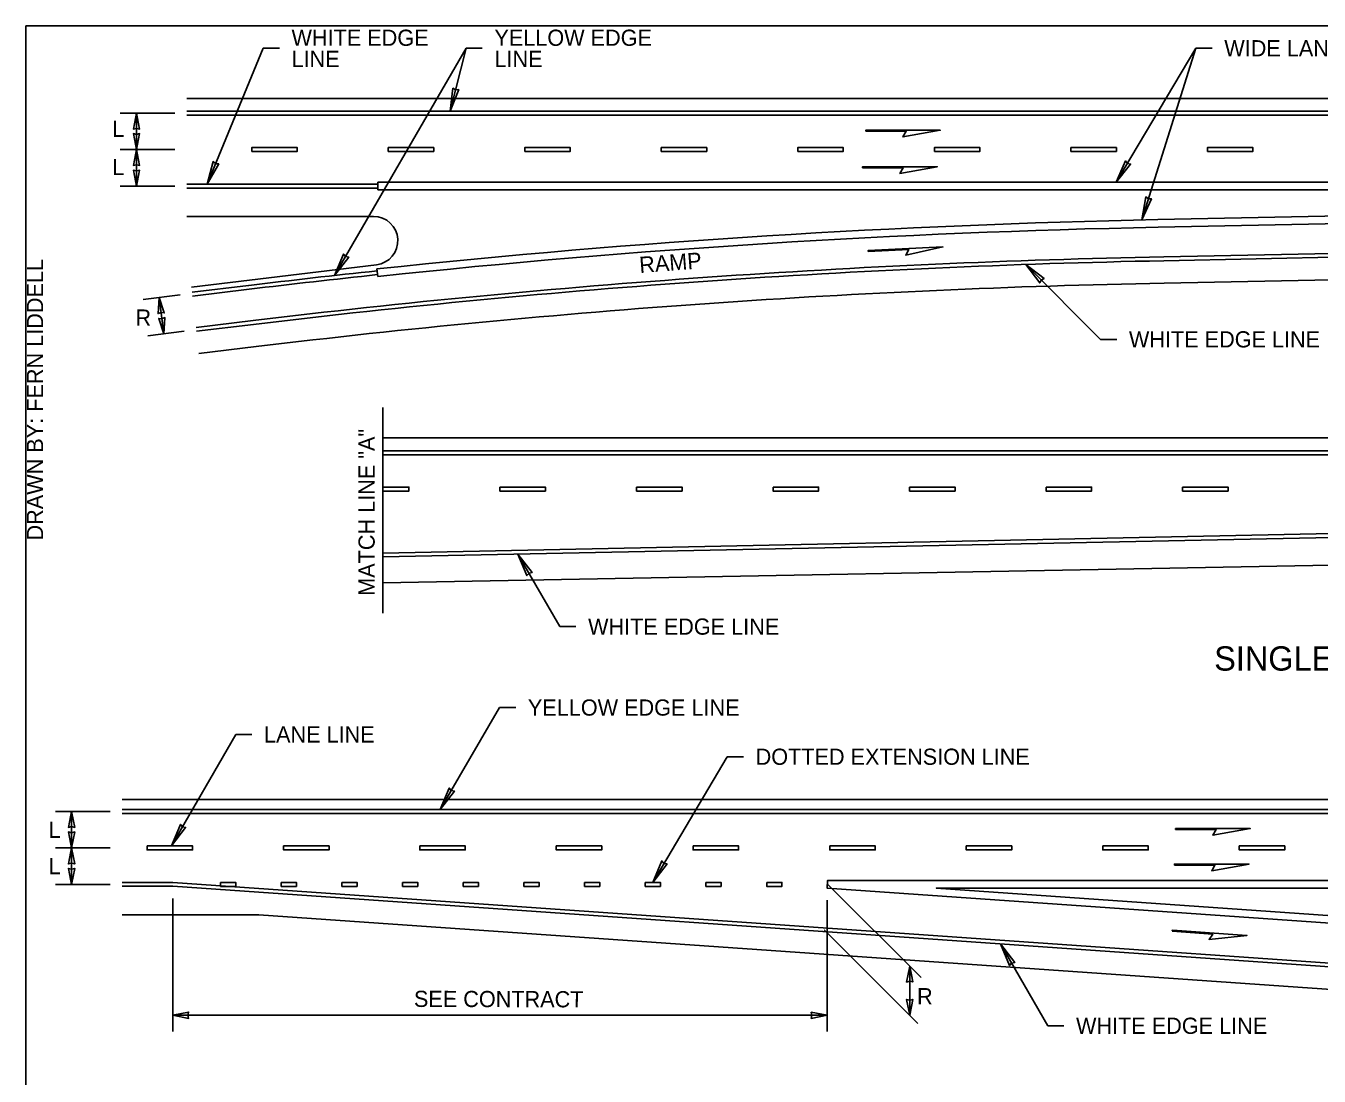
# Model space of a CAD drawing. Extents: x 99862 to 103151, y 100164 to 102240.
# Drawn here: x 99862 to 101141, y 101202 to 102240 of the extents above; entities that cross this region are included whole.
import ezdxf

# ---------------------------------------------------------------- set-up
doc = ezdxf.new("R2010")
doc.units = 0
for name, color, linetype in [('Level 1', 7, 'Continuous'), ('Level 15', 7, 'Continuous'), ('Level 2', 7, 'Continuous'), ('Level 20', 7, 'Continuous'), ('Level 3', 7, 'Continuous'), ('Level 4', 7, 'Continuous'), ('Level 5', 7, 'Continuous'), ('Level 6', 7, 'Continuous'), ('Level 62', 7, 'Continuous')]:
    doc.layers.add(name, color=color, linetype=linetype)

msp = doc.modelspace()

# ---------------------------------------------------------------- linework, layer by layer
at = {"layer": 'Level 1'}
msp.add_lwpolyline([(99862, 100164.2), (103151, 100164.2), (103151, 102240.2), (99862, 102240.2)], close=True, dxfattribs=at)
at = {"layer": 'Level 15'}
for p, q in [((100096.7, 102218.1), (100041.3, 102083.9)), ((100112.7, 102218.1), (100096.7, 102218.1)), ((100297.3, 102218.1), (100167.3, 101993.5)), ((100297.3, 102218.1), (100281.6, 102155.8)), ((100313.3, 102218.1), (100297.3, 102218.1)), ((100940.1, 102085.6), (101019, 102218.1)), ((100965.3, 102048.4), (101019, 102218.1)), ((101035, 102218.1), (101019, 102218.1)), ((99955.3, 102153.9), (100009.3, 102153.9)), ((99971.3, 102153.9), (99971.3, 102118)), ((99955.3, 102118), (100009.3, 102118)), ((99971.3, 102118), (99971.3, 102081.9)), ((99955.3, 102081.9), (100009.3, 102081.9)), ((100850.6, 102004.4), (100924.7, 101930.4)), ((99978, 101969.7), (100014.7, 101974.5)), ((99993.8, 101971.7), (99998.5, 101935.9)), ((99982.6, 101933.8), (100018.6, 101938.5)), ((100924.7, 101930.4), (100940.7, 101930.4)), ((100389.9, 101646.5), (100348.6, 101718.2)), ((100389.9, 101646.5), (100405.9, 101646.5)), ((100271.8, 101465.6), (100330.4, 101566.5)), ((100330.4, 101566.5), (100346.4, 101566.5)), ((100005.9, 101429.7), (100069.5, 101539.9)), ((100069.5, 101539.9), (100085.5, 101539.9)), ((100482, 101393.6), (100555.6, 101517.9)), ((100555.6, 101517.9), (100571.6, 101517.9)), ((99945.2, 101463.7), (99891.2, 101463.7)), ((99907.2, 101463.7), (99907.2, 101427.7)), ((99945.2, 101427.7), (99891.2, 101427.7)), ((99907.2, 101427.7), (99907.2, 101391.7)), ((99945.2, 101391.7), (99891.2, 101391.7)), ((100747.2, 101299.7), (100655.1, 101391.7)), ((100007.2, 101377.9), (100007.2, 101246.4)), ((100654.2, 101376), (100654.2, 101246.4)), ((100744, 101254.3), (100651.4, 101346.9)), ((100825.8, 101332.8), (100872.4, 101252)), ((100735.9, 101311), (100735.9, 101262.4)), ((100654.2, 101262.4), (100007.2, 101262.4)), ((100872.4, 101252), (100888.4, 101252))]:
    msp.add_line(p, q, dxfattribs=at)
for points in [[(100281.6, 102155.8), (100290.1, 102177.2), (100286.9, 102176.9), (100284.3, 102178.6)], [(99971.3, 102153.9), (99974.4, 102138.2), (99971.3, 102138.9), (99968.3, 102138.2)], [(99971.3, 102118), (99968.3, 102133.8), (99971.3, 102133), (99974.4, 102133.8)], [(99971.3, 102118), (99974.4, 102102.3), (99971.3, 102103), (99968.3, 102102.3)], [(99971.3, 102081.9), (99968.3, 102097.6), (99971.3, 102096.9), (99974.4, 102097.6)], [(100041.3, 102083.9), (100047.3, 102106.1), (100049.7, 102104), (100052.8, 102103.8)], [(100940.1, 102085.6), (100954.3, 102103.7), (100951.2, 102104.3), (100949.2, 102106.8)], [(100965.3, 102048.4), (100969.3, 102071.1), (100971.9, 102069.2), (100975, 102069.3)], [(100167.3, 101993.5), (100176.1, 102014.7), (100178.2, 102012.3), (100181.3, 102011.7)], [(100850.6, 102004.4), (100868.8, 101990.4), (100866, 101989), (100864.6, 101986.2)], [(99993.8, 101971.7), (99998.9, 101956.6), (99995.8, 101956.9), (99992.8, 101955.8)], [(99998.5, 101935.9), (99999.5, 101951.9), (99996.6, 101950.8), (99993.4, 101951.1)], [(100348.6, 101718.2), (100357.4, 101696.9), (100359.5, 101699.3), (100362.6, 101699.9)], [(100271.8, 101465.6), (100285.8, 101483.9), (100282.6, 101484.5), (100280.6, 101486.9)], [(99907.2, 101463.7), (99910.3, 101448), (99907.2, 101448.8), (99904.1, 101448)], [(100005.9, 101429.7), (100019.9, 101448), (100016.8, 101448.6), (100014.8, 101451)], [(99907.2, 101427.7), (99910.3, 101443.5), (99907.2, 101442.7), (99904.1, 101443.5)], [(99907.2, 101427.7), (99910.3, 101412), (99907.2, 101412.8), (99904.1, 101412)], [(99907.2, 101391.7), (99910.3, 101407.5), (99907.2, 101406.7), (99904.1, 101407.5)], [(100482, 101393.6), (100496, 101411.9), (100492.8, 101412.5), (100490.8, 101414.9)], [(100825.8, 101332.8), (100839.8, 101314.5), (100836.6, 101313.9), (100834.6, 101311.5)], [(100735.9, 101311), (100739, 101295.3), (100735.9, 101296), (100732.8, 101295.2)], [(100735.9, 101262.4), (100739, 101278.1), (100735.9, 101277.4), (100732.8, 101278.1)], [(100007.2, 101262.4), (100022.9, 101265.5), (100022.2, 101262.4), (100022.9, 101259.3)], [(100654.2, 101262.4), (100638.5, 101259.3), (100639.2, 101262.4), (100638.5, 101265.4)]]:
    msp.add_lwpolyline(points, close=True, dxfattribs=at)
at = {"layer": 'Level 2'}
for p, q in [((100021.3, 102168.6), (103073.2, 102168.6)), ((100021.3, 102051.9), (100205.8, 102051.9)), ((103073.2, 102025.3), (100987.6, 101986)), ((100208.7, 102004.1), (100025.9, 101982)), ((100089.7, 101923.2), (100033.1, 101916.4)), ((100214.9, 101833), (101672, 101833)), ((100214.9, 101689.7), (101627, 101716.3)), ((103047.3, 101475.7), (99957.2, 101475.7))]:
    msp.add_line(p, q, dxfattribs=at)
msp.add_lwpolyline([(99957.2, 101361.7), (100092.5, 101361.7), (102028.7, 101226.8)], dxfattribs=at)
for centre, radius, start, end in [((100205.8, 102027.9), 24, 276.8849, 90), ((101161.4, 93047.7), 8940, 91.11404, 96.88493)]:
    msp.add_arc(centre, radius, start, end, dxfattribs=at)
at = {"layer": 'Level 3'}
for p, q in [((100021.3, 102155.8), (103073.2, 102155.8)), ((103073.2, 102152), (100021.3, 102152)), ((100209.9, 102085.6), (100209.9, 102078.1)), ((100209.9, 102083.9), (100021.3, 102083.9)), ((100209.9, 102079.9), (100021.3, 102079.9)), ((100209.9, 102078.1), (101856.6, 102078.1)), ((103073.2, 102054.7), (100987.1, 102011.9)), ((100987.2, 102008.1), (103073.2, 102051)), ((100209.1, 102000), (100209.9, 101992.6)), ((100082.3, 101983.6), (100026.4, 101976.9)), ((100026.8, 101973.1), (100082.8, 101979.9)), ((100086.6, 101948.9), (100030.3, 101942.1)), ((100030.7, 101938.4), (100087.1, 101945.2)), ((101672, 101820.2), (100214.9, 101820.2)), ((100214.9, 101816.4), (101672, 101816.4)), ((101627, 101748.2), (100214.9, 101719.2)), ((100214.9, 101715.4), (101627, 101744.4)), ((103047.3, 101465.6), (99957.2, 101465.6)), ((99957.2, 101461.9), (103047.3, 101461.9))]:
    msp.add_line(p, q, dxfattribs=at)
for points in [[(101856.6, 102078.1), (101856.6, 102085.6), (100209.9, 102085.6)], [(100981.5, 102041.3), (101856.8, 102058.8), (101856.6, 102066.3), (100981.4, 102048.7)], [(102030.7, 101252.5), (100007.3, 101393.6), (99957.2, 101393.6)], [(99957.2, 101389.9), (100007.2, 101389.9), (102030.5, 101248.8)]]:
    msp.add_lwpolyline(points, dxfattribs=at)
msp.add_lwpolyline([(101774.5, 101388), (101774.5, 101395.5), (100654.5, 101395.5), (100654.2, 101388), (101772.2, 101310.1), (101772.7, 101317.6), (100762.2, 101388)], close=True, dxfattribs=at)
for centre, radius, start, end in [((101161.4, 93046.8), 9003.7, 91.14576, 96.07141), ((101161.4, 93046.8), 8996.2, 91.14576, 96.07144), ((101161.4, 93047.7), 8965.9, 91.11413, 96.88493), ((101161.4, 93047.7), 8962.1, 91.11413, 96.88493), ((101161.5, 93046.7), 9001.9, 96.07144, 96.88493), ((101161.5, 93046.7), 8998.1, 96.07149, 96.88493)]:
    msp.add_arc(centre, radius, start, end, dxfattribs=at)
at = {"layer": 'Level 4'}
for points in [[(100085.3, 102116.1), (100130.3, 102116.1), (100130.3, 102120), (100085.3, 102120)], [(100220.3, 102116.1), (100265.3, 102116.1), (100265.3, 102120), (100220.3, 102120)], [(100355.3, 102116.1), (100400.3, 102116.1), (100400.3, 102120), (100355.3, 102120)], [(100490.3, 102116.1), (100535.3, 102116.1), (100535.3, 102120), (100490.3, 102120)], [(100625.3, 102116.1), (100670.3, 102116.1), (100670.3, 102120), (100625.3, 102120)], [(100760.3, 102116.1), (100805.3, 102116.1), (100805.3, 102120), (100760.3, 102120)], [(100895.3, 102116.1), (100940.3, 102116.1), (100940.3, 102120), (100895.3, 102120)], [(101030.3, 102116.1), (101075.3, 102116.1), (101075.3, 102120), (101030.3, 102120)], [(100330.8, 101784.4), (100375.8, 101784.4), (100375.8, 101780.5), (100330.8, 101780.5)], [(100465.8, 101784.4), (100510.8, 101784.4), (100510.8, 101780.5), (100465.8, 101780.5)], [(100600.8, 101784.4), (100645.8, 101784.4), (100645.8, 101780.5), (100600.8, 101780.5)], [(100735.8, 101784.4), (100780.8, 101784.4), (100780.8, 101780.5), (100735.8, 101780.5)], [(100870.8, 101784.4), (100915.8, 101784.4), (100915.8, 101780.5), (100870.8, 101780.5)], [(101005.8, 101784.4), (101050.8, 101784.4), (101050.8, 101780.5), (101005.8, 101780.5)], [(99981.9, 101429.7), (100026.9, 101429.7), (100026.9, 101425.8), (99981.9, 101425.8)], [(100116.9, 101429.7), (100161.9, 101429.7), (100161.9, 101425.8), (100116.9, 101425.8)], [(100251.4, 101429.7), (100296.4, 101429.7), (100296.4, 101425.8), (100251.4, 101425.8)], [(100386.4, 101429.7), (100431.4, 101429.7), (100431.4, 101425.8), (100386.4, 101425.8)], [(100521.8, 101429.7), (100566.8, 101429.7), (100566.8, 101425.8), (100521.8, 101425.8)], [(100656.8, 101429.7), (100701.8, 101429.7), (100701.8, 101425.8), (100656.8, 101425.8)], [(100791.8, 101429.7), (100836.8, 101429.7), (100836.8, 101425.8), (100791.8, 101425.8)], [(100926.8, 101429.7), (100971.8, 101429.7), (100971.8, 101425.8), (100926.8, 101425.8)], [(101061.8, 101429.7), (101106.8, 101429.7), (101106.8, 101425.8), (101061.8, 101425.8)], [(100054.5, 101393.6), (100069.5, 101393.6), (100069.5, 101389.7), (100054.5, 101389.7)], [(100114.5, 101393.6), (100129.5, 101393.6), (100129.5, 101389.7), (100114.5, 101389.7)], [(100174.5, 101393.6), (100189.5, 101393.6), (100189.5, 101389.7), (100174.5, 101389.7)], [(100234.5, 101393.6), (100249.5, 101393.6), (100249.5, 101389.7), (100234.5, 101389.7)], [(100294.5, 101393.6), (100309.5, 101393.6), (100309.5, 101389.7), (100294.5, 101389.7)], [(100354.5, 101393.6), (100369.5, 101393.6), (100369.5, 101389.7), (100354.5, 101389.7)], [(100414.5, 101393.6), (100429.5, 101393.6), (100429.5, 101389.7), (100414.5, 101389.7)], [(100474.5, 101393.6), (100489.5, 101393.6), (100489.5, 101389.7), (100474.5, 101389.7)], [(100534.5, 101393.6), (100549.5, 101393.6), (100549.5, 101389.7), (100534.5, 101389.7)], [(100594.5, 101393.6), (100609.5, 101393.6), (100609.5, 101389.7), (100594.5, 101389.7)]]:
    msp.add_lwpolyline(points, close=True, dxfattribs=at)
msp.add_lwpolyline([(100214.9, 101784.4), (100240.8, 101784.4), (100240.8, 101780.5), (100214.9, 101780.5)], dxfattribs=at)
at = {"layer": 'Level 5'}
for points in [[(100692.4, 102136), (100732.5, 102136), (100729.3, 102130.5), (100766.2, 102137), (100692.4, 102137)], [(100689.3, 102099.9), (100729.4, 102099.9), (100726.2, 102094.4), (100763.1, 102101), (100689.3, 102101)], [(100695, 102017.3), (100735, 102019.2), (100732.1, 102013.6), (100768.7, 102021.8), (100694.9, 102018.3)], [(100998.9, 101445.8), (101038.9, 101445.8), (101035.8, 101440.3), (101072.7, 101446.8), (100998.9, 101446.8)], [(100997.7, 101410.6), (101037.7, 101410.6), (101034.6, 101405.2), (101071.5, 101411.7), (100997.7, 101411.7)], [(100995.6, 101345.4), (101035.6, 101342.6), (101032, 101337.3), (101069.3, 101341.3), (100995.7, 101346.4)]]:
    msp.add_lwpolyline(points, close=True, dxfattribs=at)
at = {"layer": 'Level 6'}
msp.add_line((100214.9, 101659.7), (100214.9, 101863), dxfattribs=at)

# ---------------------------------------------------------------- texts
at = {"layer": 'Level 20'}
for s, rotation, p in [('WHITE EDGE', 360, (100124.7, 102220.5)), ('YELLOW EDGE', 360, (100325.3, 102220.5)), ('WIDE LANE LINE', 360, (101047, 102210.1)), ('LINE', 360, (100124.7, 102199.6)), ('LINE', 360, (100325.3, 102199.6)), ('RAMP', 4.3279, (100469.1, 101995.9)), ('MATCH LINE "A"', 90, (100206.9, 101676.9)), ('SEE CONTRACT', 359.8449, (100245.7, 101270.6))]:
    msp.add_text(s, height=16, rotation=rotation, dxfattribs=at).set_placement(p)
for s, height, p in [('L', 16, (99947.5, 102130.5)), ('L', 16, (99947.5, 102092.8)), ('R', 16, (99970.4, 101943.9)), ('WHITE EDGE LINE', 16, (100952.7, 101922.4)), ('WHITE EDGE LINE', 16, (100417.9, 101638.5)), ('SINGLE-LANE TAPERED ON-CONNECTION', 24, (101037, 101603)), ('YELLOW EDGE LINE', 16, (100358.4, 101558.5)), ('LANE LINE', 16, (100097.5, 101531.9)), ('DOTTED EXTENSION LINE', 16, (100583.6, 101509.9)), ('L', 16, (99884.5, 101437.7)), ('L', 16, (99884.5, 101401.7)), ('R', 16, (100743.2, 101273.2)), ('WHITE EDGE LINE', 16, (100900.4, 101244))]:
    msp.add_text(s, height=height, dxfattribs=at).set_placement(p)
at = {"layer": 'Level 62'}
msp.add_text('DRAWN BY: FERN LIDDELL', height=16, rotation=90, dxfattribs=at).set_placement((99879, 101731.6))

doc.saveas('drawing.dxf')
